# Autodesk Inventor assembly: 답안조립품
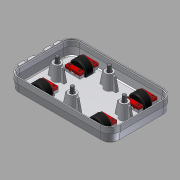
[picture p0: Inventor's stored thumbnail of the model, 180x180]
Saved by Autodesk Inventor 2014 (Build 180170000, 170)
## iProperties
Created: 2015-06
Part Number: 답안조립품
Document SubType Name: Assembly
Designer: Administrator
Author: Administrator
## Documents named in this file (6)
- C:\Documents and Settings\Administrator\바탕 화면\450508V1036\답안조립품.iam
- C:\Documents and Settings\Administrator\바탕 화면\450508V1036\본체.ipt
- C:\Documents and Settings\Administrator\바탕 화면\450508V1036\커버.ipt
- C:\Documents and Settings\Administrator\바탕 화면\450508V1036\M4x10.ipt
- C:\Documents and Settings\Administrator\바탕 화면\450508V1036\바퀴.ipt
- C:\Documents and Settings\Administrator\바탕 화면\450508V1036\바퀴고정부.ipt
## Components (4 placed, 1 different names)
1. M4x10:1
2. M4x10:2
3. M4x10:3
4. M4x10:4
